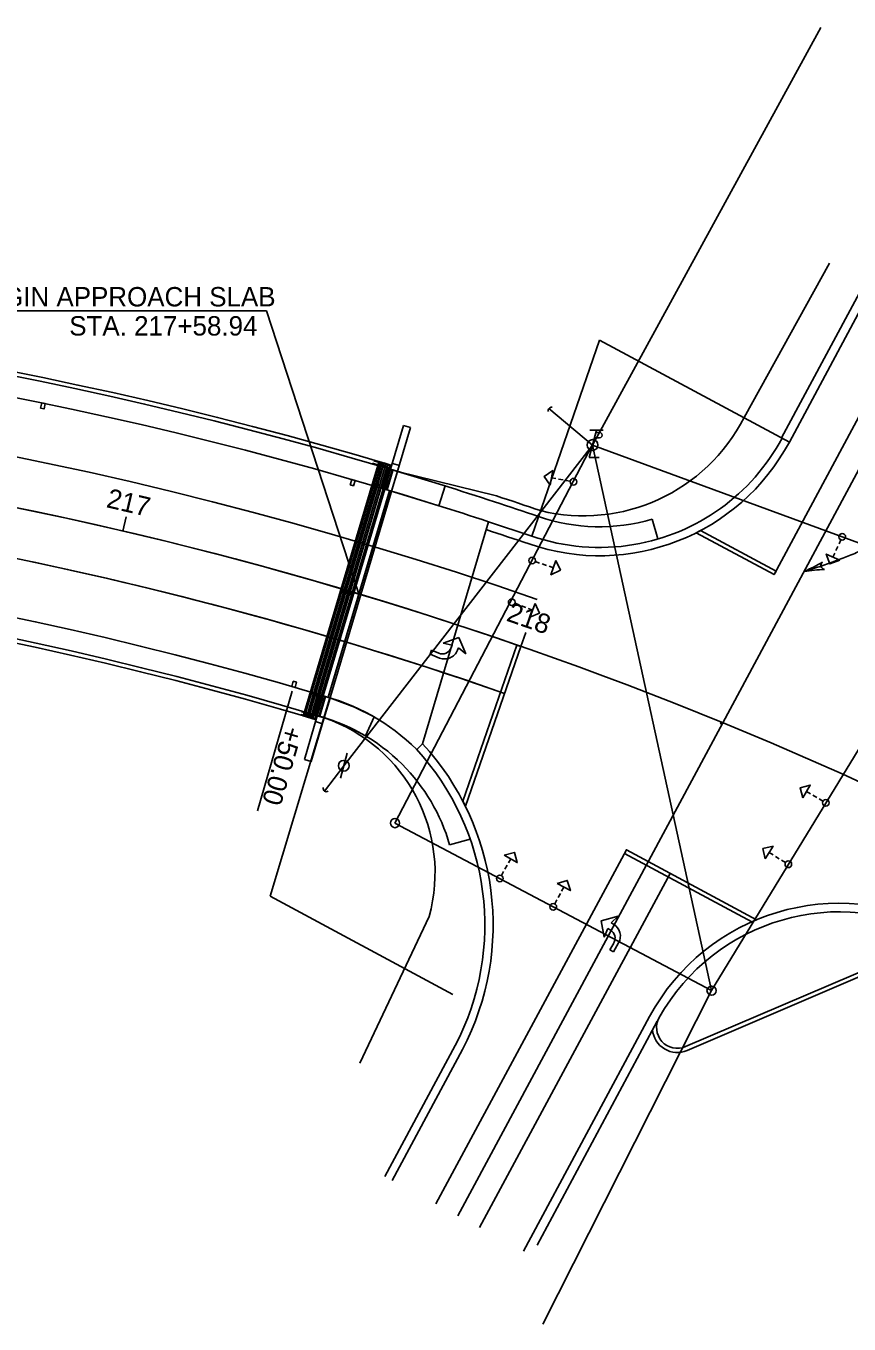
# Model space of a CAD drawing. Extents: x 10803 to 14007, y 6159 to 7440.
# Drawn here: x 12720.1 to 12918.6, y 6513.8 to 6826.9 of the extents above; entities that cross this region are included whole.
import ezdxf

# ---------------------------------------------------------------- set-up
doc = ezdxf.new("R2010")
doc.units = 0
for name, color, linetype in [('BR_P_Beam_Stl_Det', 7, 'Continuous'), ('BR_P_Beam_Stl_Det_Hidden', 7, 'Continuous'), ('BR_P_Rail_Object', 7, 'Continuous'), ('BR_P_Slab_Hidden', 7, 'Continuous'), ('BR_P_Slab_Object', 7, 'Continuous'), ('BR_P_Slab_Reinforcing', 7, 'Continuous'), ('BR_P_Sub_Hidden', 7, 'Continuous'), ('BR_P_Sub_Object', 7, 'Continuous'), ('BR_X_Drain_Object', 7, 'Continuous'), ('BR_X_Gen_Approach_Slab', 7, 'Continuous'), ('BR_X_Rail_Object', 7, 'Continuous'), ('BR_X_Rail_Reinforcing', 7, 'Continuous'), ('BR_X_Slab_Object', 7, 'Continuous'), ('BR_X_Sub_Object', 7, 'Continuous'), ('Default', 7, 'Continuous'), ('GE_X_Alignment', 7, 'Continuous'), ('GE_X_Alignment_100_Stations', 7, 'Continuous'), ('MT_X_Cells', 7, 'Continuous'), ('PM_X_Cells', 7, 'Continuous'), ('PM_X_Channelizing_Line', 7, 'Continuous'), ('PM_X_CL_Double_Solid', 7, 'Continuous'), ('PM_X_Lane_Line', 7, 'Continuous'), ('PM_X_Stop_Line', 7, 'Continuous'), ('PV_X_Curb', 7, 'Continuous'), ('PV_X_Walk', 7, 'Continuous'), ('RD_X_GR_Lt', 7, 'Continuous'), ('SC_Scratch1', 7, 'Continuous'), ('SG_X_Heads', 7, 'Continuous'), ('UT_X_Electric', 7, 'Continuous'), ('UT_X_Misc_Cells', 7, 'Continuous'), ('UT_X_Overhead_Combined', 7, 'Continuous'), ('UT_X_Overhead_Telecom', 7, 'Continuous'), ('UT_X_Unknown_Cells', 7, 'Continuous')]:
    doc.layers.add(name, color=color, linetype=linetype)

msp = doc.modelspace()

# ---------------------------------------------------------------- linework, layer by layer
at = {"layer": 'BR_P_Beam_Stl_Det'}
for p, q in [((12805.88, 6715.43), (12807.28, 6720.15)), ((12807, 6715.09), (12808.4, 6719.8)), ((12808.48, 6719.78), (12807.08, 6715.07)), ((12808.56, 6719.75), (12807.16, 6715.05)), ((12807.28, 6720.15), (12808.56, 6719.75)), ((12806.3, 6715.3), (12791.47, 6665.43)), ((12806.5, 6715.24), (12791.67, 6665.37)), ((12805.88, 6715.43), (12807.16, 6715.05)), ((12791.05, 6665.56), (12789.64, 6660.84)), ((12792.17, 6665.22), (12790.76, 6660.52)), ((12790.84, 6660.49), (12792.25, 6665.2)), ((12790.92, 6660.47), (12792.33, 6665.17)), ((12791.05, 6665.56), (12792.33, 6665.17)), ((12789.64, 6660.84), (12790.92, 6660.47))]:
    msp.add_line(p, q, dxfattribs=at)
for centre in [(12807.41, 6719.84), (12806.41, 6716.49), (12806.55, 6716.96), (12806.7, 6717.44), (12806.84, 6717.92), (12806.98, 6718.4), (12807.12, 6718.88), (12807.27, 6719.36), (12806.13, 6715.53), (12806.27, 6716.01), (12790.63, 6663.42), (12790.77, 6663.9), (12790.91, 6664.38), (12791.06, 6664.86), (12791.2, 6665.34), (12789.91, 6661.03), (12790.05, 6661.5), (12790.2, 6661.98), (12790.34, 6662.46), (12790.48, 6662.94)]:
    msp.add_circle(centre, 0.0833, dxfattribs=at)
at = {"layer": 'BR_P_Beam_Stl_Det_Hidden'}
for p, q in [((12805.84, 6715.44), (12807.24, 6720.16)), ((12807.7, 6720.02), (12806.3, 6715.3)), ((12807.9, 6719.96), (12806.5, 6715.24)), ((12807.28, 6720.15), (12807.24, 6720.16)), ((12808, 6719.93), (12807.6, 6720.05)), ((12791.01, 6665.57), (12789.6, 6660.85)), ((12790.06, 6660.72), (12791.47, 6665.43)), ((12790.26, 6660.66), (12791.67, 6665.37)), ((12789.64, 6660.84), (12789.6, 6660.85)), ((12790.36, 6660.63), (12789.96, 6660.75))]:
    msp.add_line(p, q, dxfattribs=at)
at = {"layer": 'BR_P_Rail_Object'}
for p, q in [((12804.91, 6720.93), (12805.19, 6721.89)), ((12804.91, 6720.93), (12807.78, 6720.08)), ((12805.19, 6721.89), (12808.07, 6721.04)), ((12807.78, 6720.08), (12808.07, 6721.04)), ((12787.24, 6661.5), (12786.95, 6660.54)), ((12786.95, 6660.54), (12789.83, 6659.69)), ((12787.24, 6661.5), (12790.1, 6660.61)), ((12790.1, 6660.61), (12789.83, 6659.69))]:
    msp.add_line(p, q, dxfattribs=at)
at = {"layer": 'BR_P_Slab_Hidden'}
for p, q in [((12806.2, 6715.33), (12807.62, 6720.12)), ((12791.37, 6665.46), (12789.94, 6660.67))]:
    msp.add_line(p, q, dxfattribs=at)
at = {"layer": 'BR_P_Slab_Object'}
for p, q in [((12787.24, 6661.5), (12804.91, 6720.93)), ((12791.37, 6665.46), (12806.2, 6715.33)), ((12803.48, 6716.14), (12806.36, 6715.28)), ((12788.66, 6666.29), (12791.37, 6665.46))]:
    msp.add_line(p, q, dxfattribs=at)
at = {"layer": 'BR_P_Slab_Reinforcing'}
for p, q in [((12787.32, 6660.61), (12805.46, 6721.64)), ((12787.8, 6660.47), (12805.94, 6721.49)), ((12788.28, 6660.32), (12806.42, 6721.35)), ((12788.76, 6660.18), (12806.9, 6721.21)), ((12789.24, 6660.04), (12807.38, 6721.07)), ((12805.59, 6720.9), (12805.78, 6721.54)), ((12806.63, 6720.59), (12806.82, 6721.23)), ((12807.67, 6720.28), (12807.86, 6720.92)), ((12803.94, 6716.85), (12803.75, 6716.22)), ((12804.41, 6716.69), (12804.22, 6716.06)), ((12804.9, 6716.54), (12804.7, 6715.9)), ((12805.37, 6716.4), (12805.18, 6715.77)), ((12805.85, 6716.26), (12805.66, 6715.62)), ((12788.67, 6665.46), (12788.86, 6666.09)), ((12789.15, 6665.32), (12789.34, 6665.95)), ((12789.62, 6665.18), (12789.81, 6665.81)), ((12790.11, 6665.02), (12790.3, 6665.66)), ((12790.58, 6664.87), (12790.77, 6665.5)), ((12786.36, 6660.89), (12789.71, 6659.9)), ((12787.83, 6661.15), (12787.64, 6660.52)), ((12788.87, 6660.85), (12788.68, 6660.21)), ((12789.9, 6660.54), (12789.71, 6659.9))]:
    msp.add_line(p, q, dxfattribs=at)
for points in [[(12796.47, 6691.1), (12796.31, 6691.15), (12796.07, 6690.33), (12796.23, 6690.28)], [(12796.95, 6690.96), (12796.79, 6691), (12796.54, 6690.19), (12796.71, 6690.14)], [(12797.43, 6690.81), (12797.27, 6690.86), (12797.02, 6690.04), (12797.19, 6690)], [(12797.91, 6690.67), (12797.75, 6690.72), (12797.5, 6689.9), (12797.67, 6689.85)], [(12798.39, 6690.53), (12798.23, 6690.58), (12797.98, 6689.76), (12798.15, 6689.71)]]:
    msp.add_lwpolyline(points, close=True, dxfattribs=at)
for centre in [(12803.75, 6716.22), (12804.22, 6716.06), (12804.7, 6715.9), (12805.18, 6715.77), (12805.66, 6715.62), (12788.86, 6666.09), (12789.34, 6665.95), (12789.81, 6665.81), (12790.3, 6665.66), (12790.77, 6665.5)]:
    msp.add_circle(centre, 0.0417, dxfattribs=at)
msp.add_arc((12526.06, 5775.26), 923.76, 73.40383, 73.62298, dxfattribs=at)
at = {"layer": 'BR_P_Sub_Hidden'}
for p, q in [((12808.02, 6720.01), (12806.6, 6715.21)), ((12790.33, 6660.55), (12791.77, 6665.34))]:
    msp.add_line(p, q, dxfattribs=at)
at = {"layer": 'BR_P_Sub_Object'}
for p, q in [((12809.69, 6719.49), (12808.02, 6720.01)), ((12808.27, 6714.71), (12809.69, 6719.49)), ((12806.6, 6715.21), (12791.77, 6665.34)), ((12792.96, 6664.98), (12807.8, 6714.85)), ((12806.6, 6715.21), (12808.27, 6714.71)), ((12793.44, 6664.83), (12791.77, 6665.34)), ((12791.77, 6665.34), (12793.45, 6664.85)), ((12792.03, 6660.07), (12793.44, 6664.83)), ((12790.35, 6660.57), (12792.03, 6660.07))]:
    msp.add_line(p, q, dxfattribs=at)
at = {"layer": 'BR_X_Drain_Object'}
for points in [[(12723.6, 6734.73), (12724.42, 6734.56), (12724.69, 6735.86), (12723.87, 6736.03)], [(12798.24, 6716.29), (12799.04, 6716.04), (12799.44, 6717.31), (12798.65, 6717.56)], [(12784.17, 6667.6), (12784.97, 6667.37), (12785.35, 6668.65), (12784.55, 6668.89)]]:
    msp.add_lwpolyline(points, close=True, dxfattribs=at)
at = {"layer": 'BR_X_Gen_Approach_Slab'}
for p, q in [((12815.72, 6653.82), (12831.65, 6707.37)), ((12814.31, 6652.4), (12815.72, 6653.82))]:
    msp.add_line(p, q, dxfattribs=at)
for centre, radius, start, end in [((12526.06, 5775.26), 980.93, 71.84836, 73.38159), ((12779, 6617), 50, 45.0732, 76.3482)]:
    msp.add_arc(centre, radius, start, end, dxfattribs=at)
at = {"layer": 'BR_X_Rail_Object'}
for radius, start, end in [(986.93, 73.39646, 105.444), (985.93, 73.44, 105.39238), (923.93, 73.39349, 107.88018), (922.93, 73.39344, 107.88024)]:
    msp.add_arc((12526.06, 5775.26), radius, start, end, dxfattribs=at)
at = {"layer": 'BR_X_Rail_Reinforcing'}
msp.add_line((12803.97, 6722.08), (12807.86, 6720.92), dxfattribs=at)
msp.add_arc((12526.06, 5775.26), 986.09, 73.40611, 73.64869, dxfattribs=at)
at = {"layer": 'BR_X_Slab_Object'}
msp.add_line((12789.83, 6659.69), (12808.07, 6721.04), dxfattribs=at)
for radius, start, end in [(980.93, 73.3962, 105.57342), (928.93, 73.5225, 107.61257)]:
    msp.add_arc((12526.06, 5775.26), radius, start, end, dxfattribs=at)
at = {"layer": 'BR_X_Sub_Object'}
for p, q in [((12788.89, 6649.53), (12812.83, 6730.05)), ((12808.02, 6720.01), (12811.16, 6730.55)), ((12812.83, 6730.05), (12811.16, 6730.55)), ((12788.15, 6660.19), (12806.39, 6721.53)), ((12806.39, 6721.53), (12808.31, 6720.96)), ((12808.45, 6721.44), (12810.13, 6720.94)), ((12792.97, 6665.01), (12807.79, 6714.85)), ((12787.22, 6650.04), (12790.34, 6660.55)), ((12788.15, 6660.19), (12790.07, 6659.62)), ((12789.92, 6659.14), (12791.6, 6658.64)), ((12788.89, 6649.53), (12787.22, 6650.04))]:
    msp.add_line(p, q, dxfattribs=at)
at = {"layer": 'Default'}
for p, q in [((12888.2, 6658.85), (12961.64, 6795.9)), ((12789.11, 6659.9), (12807.35, 6721.25)), ((12831.65, 6707.37), (12842.05, 6703.89)), ((12912.2, 6697.62), (12912.2, 6697.62)), ((12789.39, 6660.86), (12791.95, 6660.1)), ((12824.21, 6539.96), (12888.2, 6658.85)), ((12887.54, 6658.75), (12887.54, 6658.75)), ((12822.26, 6629.39), (12827.21, 6630.81)), ((12808.36, 6548.49), (12825.35, 6580.06))]:
    msp.add_line(p, q, dxfattribs=at)
msp.add_lwpolyline([(12800.38, 6689.93), (12778.07, 6758.21), (12694.59, 6758.21)], dxfattribs=at)
for points in [[(12808.27, 6714.71), (12809.69, 6719.49), (12821.18, 6715.98), (12819.66, 6711.21), (12810.99, 6713.89)], [(12793.45, 6664.86), (12793.39, 6664.89), (12799.34, 6662.65), (12804.04, 6660.28), (12801.93, 6655.72), (12799.33, 6657.13), (12796.36, 6658.52), (12791.95, 6660.1), (12792.03, 6660.07)]]:
    msp.add_lwpolyline(points, close=True, dxfattribs=at)
for centre, radius, start, end in [((12858.38, 6751.15), 50, 250.9447, 279.5926), ((12893.34, 6729.23), 36.8, 293.0768, 300.8313), ((12913.75, 6659.05), 36.8, 91.5971, 99.3515), ((12887.13, 6663.64), 4.91, 274.7857, 282.5401), ((12890.37, 6654.45), 4.91, 116.2654, 124.0199)]:
    msp.add_arc(centre, radius, start, end, dxfattribs=at)
for centre, major_axis, start_param, end_param in [((12913.08, 6696.92), (-1.2, -0.35), 5.265733, 7.307734), ((12887.5, 6658.61), (0.157, 0.055), 5.258637, 7.300638)]:
    msp.add_ellipse(centre, major_axis=major_axis, ratio=0.873734, start_param=start_param, end_param=end_param, dxfattribs=at)
msp.add_open_spline([(12907.77, 6695.37), (12933.89, 6703.1), (12947.05, 6718.99)], degree=2, dxfattribs=at)
at = {"layer": 'GE_X_Alignment'}
msp.add_arc((12526.06, 5775.26), 954.93, 61.68982, 109.40279, dxfattribs=at)
at = {"layer": 'GE_X_Alignment_100_Stations'}
for p, q in [((12743.44, 6705.11), (12744.24, 6708.53)), ((12839.45, 6677.3), (12840.6, 6680.61))]:
    msp.add_line(p, q, dxfattribs=at)
at = {"layer": 'MT_X_Cells'}
for p, q in [((12824.5, 6679.44), (12820.67, 6678.1)), ((12826.2, 6675.52), (12824.5, 6679.44)), ((12817.91, 6676.34), (12817.54, 6675.41)), ((12819.64, 6675.64), (12817.91, 6676.34)), ((12818.78, 6678.5), (12818.78, 6678.5)), ((12820.67, 6678.1), (12822.89, 6677.57)), ((12822.89, 6677.57), (12822.62, 6676.92)), ((12824.12, 6676.35), (12824.37, 6676.97)), ((12824.37, 6676.97), (12826.2, 6675.52)), ((12817.54, 6675.41), (12819.83, 6674.48)), ((12826.2, 6675.52), (12826.2, 6675.52))]:
    msp.add_line(p, q, dxfattribs=at)
for centre, radius, end in [((12820.49, 6677.77), 2.3, 338.0984), ((12821.06, 6677.53), 3.28, 339.0068)]:
    msp.add_arc(centre, radius, 248.0984, end, dxfattribs=at)
at = {"layer": 'PM_X_Cells'}
for p, q in [((12862.91, 6612.22), (12858.79, 6611.1)), ((12858.79, 6611.1), (12859.57, 6607.14)), ((12861.21, 6610.62), (12862.91, 6612.22)), ((12861.79, 6610.29), (12861.21, 6610.62)), ((12862.91, 6612.22), (12862.91, 6612.22)), ((12859.57, 6607.14), (12860.41, 6609.24)), ((12860.41, 6609.24), (12861.01, 6608.89)), ((12858.89, 6605.31), (12858.89, 6605.31)), ((12861.84, 6605.74), (12860.91, 6604.13)), ((12860.91, 6604.13), (12861.77, 6603.63)), ((12861.77, 6603.63), (12863.02, 6605.77))]:
    msp.add_line(p, q, dxfattribs=at)
for centre, radius, end in [((12860.18, 6607.42), 3.28, 60.7023), ((12859.86, 6606.9), 2.3, 59.7938)]:
    msp.add_arc(centre, radius, 329.7938, end, dxfattribs=at)
at = {"layer": 'PM_X_Channelizing_Line'}
for p, q in [((12900.54, 6694.59), (12956.35, 6798.73)), ((12829.49, 6537.12), (12875.47, 6622.54))]:
    msp.add_line(p, q, dxfattribs=at)
msp.add_lwpolyline([(12881.7, 6704.68), (12900.54, 6694.59), (12901.01, 6695.47), (12882.78, 6705.24)], close=True, dxfattribs=at)
msp.add_arc((12526.06, 5775.26), 942.93, 70.84141, 78.02615, dxfattribs=at)
at = {"layer": 'PM_X_CL_Double_Solid'}
msp.add_line((12818.92, 6542.8), (12864.9, 6628.23), dxfattribs=at)
msp.add_arc((12526.06, 5775.26), 954.93, 70.84141, 82.24143, dxfattribs=at)
at = {"layer": 'PM_X_Lane_Line'}
for radius in [966.93, 942.93]:
    msp.add_arc((12526.06, 5775.26), radius, 70.8415, 109.40281, dxfattribs=at)
at = {"layer": 'PM_X_Stop_Line'}
for p, q in [((12900.54, 6694.59), (12881.7, 6704.68)), ((12838.5, 6677.62), (12825.42, 6639.96)), ((12839.45, 6677.3), (12826.05, 6638.72)), ((12864.9, 6628.23), (12896.29, 6611.34))]:
    msp.add_line(p, q, dxfattribs=at)
for points in [[(12838.5, 6677.62), (12839.45, 6677.3), (12826.05, 6638.72), (12825.42, 6639.96)], [(12864.42, 6627.34), (12864.9, 6628.23), (12896.29, 6611.34), (12895.12, 6610.83)]]:
    msp.add_lwpolyline(points, close=True, dxfattribs=at)
at = {"layer": 'PV_X_Curb'}
for p, q in [((12904.21, 6726.59), (12957.99, 6826.95)), ((12902.34, 6727.59), (12944.01, 6805.35)), ((12879.14, 6580.74), (12929.51, 6602.28)), ((12879.54, 6579.82), (12929.9, 6601.36)), ((12840.06, 6531.43), (12870.5, 6587.98)), ((12843.36, 6532.83), (12872.33, 6586.89)), ((12806.6, 6549.44), (12823.59, 6581.01))]:
    msp.add_line(p, q, dxfattribs=at)
for centre, radius, start, end in [((12858.38, 6751.15), 52, 250.9447, 331.8147), ((12858.38, 6751.15), 50, 279.5926, 331.8147), ((12526.06, 5775.26), 978.93, 71.20813, 71.8451), ((12768.01, 6610.08), 64.73, 332.3671, 42.5065), ((12768.01, 6610.08), 62.73, 332.3671, 42.5065), ((12916.28, 6563.34), 52, 61.7751, 151.7094), ((12916.4, 6563.27), 50, 61.7751, 150.6427), ((12877.18, 6585.34), 5, 150.6427, 293.1512), ((12877.18, 6585.34), 6, 185.209, 293.1512)]:
    msp.add_arc(centre, radius, start, end, dxfattribs=at)
at = {"layer": 'PV_X_Walk'}
msp.add_line((12871.11, 6707.99), (12872.52, 6703.2), dxfattribs=at)
for centre, radius, start, end in [((12526.06, 5775.26), 985.93, 71.85576, 73.38189), ((12526.06, 5775.26), 985.93, 71.2076, 71.85643), ((12858.38, 6751.15), 45, 250.9447, 286.4355), ((12779, 6617), 45, 45.0733, 76.6709), ((12779, 6617), 45, 15.9784, 45.0733)]:
    msp.add_arc(centre, radius, start, end, dxfattribs=at)
at = {"layer": 'RD_X_GR_Lt'}
for p, q in [((12893.31, 6732.54), (12913.86, 6769.74)), ((12809.69, 6719.49), (12833.54, 6713.59)), ((12800.58, 6576.78), (12817.3, 6612.11))]:
    msp.add_line(p, q, dxfattribs=at)
for centre, radius, start, end in [((12854.55, 6752.28), 43.5, 256.2011, 333.0027), ((12526.06, 5775.26), 987.43, 71.2076, 71.85643), ((12779.19, 6622.67), 39.54, 344.5183, 71.0576)]:
    msp.add_arc(centre, radius, start, end, dxfattribs=at)
at = {"layer": 'SC_Scratch1'}
for p, q in [((12842.05, 6703.89), (12858.38, 6751.15)), ((12904.21, 6726.59), (12858.38, 6751.15)), ((12784.28, 6666.49), (12775.92, 6637.63)), ((12793.39, 6664.89), (12779, 6617)), ((12823.03, 6593.3), (12779, 6617))]:
    msp.add_line(p, q, dxfattribs=at)
at = {"layer": 'SG_X_Heads'}
for p, q in [((12847.91, 6717.75), (12846.82, 6717.93)), ((12849.63, 6717.45), (12848.55, 6717.63)), ((12851.35, 6717.15), (12850.27, 6717.34)), ((12915.92, 6701.4), (12915.46, 6700.4)), ((12916.64, 6702.99), (12916.19, 6701.99)), ((12842.92, 6697.74), (12843.96, 6697.38)), ((12915.19, 6699.81), (12914.73, 6698.81)), ((12844.58, 6697.18), (12845.62, 6696.82)), ((12846.23, 6696.61), (12847.28, 6696.26)), ((12837.98, 6687.68), (12839, 6687.28)), ((12839.6, 6687.04), (12840.63, 6686.64)), ((12841.23, 6686.4), (12842.25, 6685.99)), ((12909.3, 6641.72), (12908.35, 6642.28)), ((12910.81, 6640.83), (12909.86, 6641.39)), ((12912.31, 6639.95), (12911.37, 6640.5)), ((12836.46, 6625.07), (12837, 6626.02)), ((12900.29, 6626.98), (12899.36, 6627.56)), ((12901.79, 6626.06), (12900.85, 6626.64)), ((12903.28, 6625.15), (12902.34, 6625.72)), ((12834.74, 6622.02), (12835.28, 6622.98)), ((12835.6, 6623.54), (12836.14, 6624.5)), ((12848.45, 6616.71), (12848.97, 6617.69)), ((12849.27, 6618.26), (12849.78, 6619.23)), ((12847.63, 6615.17), (12848.15, 6616.14))]:
    msp.add_line(p, q, dxfattribs=at)
for points in [[(12846.51, 6716.16), (12845.05, 6718.24), (12847.13, 6719.71)], [(12847.85, 6697.97), (12848.98, 6695.69), (12846.7, 6694.56)], [(12916.36, 6698.06), (12913.98, 6697.17), (12913.09, 6699.56)], [(12842.91, 6687.67), (12843.93, 6685.33), (12841.59, 6684.32)], [(12907.44, 6640.73), (12906.8, 6643.19), (12909.26, 6643.83)], [(12898.41, 6626.02), (12897.82, 6628.5), (12900.3, 6629.09)], [(12835.43, 6626.91), (12837.88, 6627.59), (12838.56, 6625.14)], [(12848.19, 6620.07), (12850.63, 6620.82), (12851.38, 6618.39)]]:
    msp.add_lwpolyline(points, close=True, dxfattribs=at)
for centre in [(12852.14, 6717.01), (12916.98, 6703.72), (12842.16, 6697.99), (12837.23, 6687.97), (12913, 6639.54), (12903.96, 6624.73), (12834.34, 6621.32), (12847.26, 6614.46)]:
    msp.add_circle(centre, 0.8, dxfattribs=at)
at = {"layer": 'UT_X_Electric'}
for p, q in [((12856.73, 6725.86), (12846.22, 6734.66)), ((12856.73, 6725.86), (12796.71, 6648.5)), ((12796.71, 6648.5), (12792.06, 6642.4))]:
    msp.add_line(p, q, dxfattribs=at)
for centre, radius, start, end in [((12846.9, 6734.14), 0.86, 84.8032, 194.2331), ((12792.55, 6643.03), 0.796, 166.8662, 300.3983)]:
    msp.add_arc(centre, radius, start, end, dxfattribs=at)
at = {"layer": 'UT_X_Misc_Cells'}
for p, q in [((12857.7, 6729.46), (12855.93, 6722.86)), ((12859.3, 6729.46), (12856.1, 6729.46)), ((12857.19, 6727.58), (12858.39, 6727.58)), ((12857.54, 6728.86), (12858.39, 6728.86)), ((12858.33, 6722.86), (12855.93, 6722.86))]:
    msp.add_line(p, q, dxfattribs=at)
for centre, radius in [((12856.73, 6725.86), 1.3), ((12809.07, 6634.67), 1.11), ((12885.45, 6594.25), 1.11)]:
    msp.add_circle(centre, radius, dxfattribs=at)
msp.add_arc((12858.4, 6728.22), 0.638, 268.8767, 91.1233, dxfattribs=at)
at = {"layer": 'UT_X_Overhead_Combined'}
for p, q in [((12856.73, 6725.86), (12911.77, 6826.6)), ((12856.73, 6725.86), (12945.67, 6693.17)), ((12856.73, 6725.86), (12885.45, 6594.25)), ((12885.45, 6594.25), (12844.7, 6513.83))]:
    msp.add_line(p, q, dxfattribs=at)
at = {"layer": 'UT_X_Overhead_Telecom'}
for p, q in [((12809.07, 6634.67), (12856.81, 6726.16)), ((12945.67, 6693.17), (12885.45, 6594.25)), ((12885.45, 6594.25), (12809.07, 6634.67))]:
    msp.add_line(p, q, dxfattribs=at)
at = {"layer": 'UT_X_Unknown_Cells'}
msp.add_line((12797.51, 6651.5), (12795.91, 6645.5), dxfattribs=at)
msp.add_circle((12796.71, 6648.5), 1.3, dxfattribs=at)

# ---------------------------------------------------------------- texts
at = {"layer": 'Default'}
for s, p in [('BEGIN APPROACH SLAB', (12706.19, 6759.29)), ('STA. 217+58.94', (12730.49, 6752.27))]:
    msp.add_text(s, height=4.68, dxfattribs=at).set_placement(p)
at = {"layer": 'GE_X_Alignment_100_Stations'}
for s, rotation, p in [('217', 346.8414, (12739.23, 6710.9)), ('218', 340.8413, (12835.7, 6683.55))]:
    msp.add_text(s, height=4.68, rotation=rotation, dxfattribs=at).set_placement(p)
at = {"layer": 'SC_Scratch1'}
msp.add_text('+50.00', height=4.68, rotation=253.5928, dxfattribs=at).set_placement((12782.41, 6658.38))

doc.saveas('drawing.dxf')
